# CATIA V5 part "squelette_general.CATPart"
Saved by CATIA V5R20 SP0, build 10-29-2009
Part number: squelette_general
Publications: "Plan_ref", "Point_A", "Point_B", "Point_C", "Point_D", "Point_E", "Point_F", "Point_debut_bati", "Projection_point_A_bati", "Projection_point_G_bati", "Projection_point_D_bati", "Point_fin_bati", "Point_fin_bascule_2", "Point_G"
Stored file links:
  C:\Users\J\IAO_2012_jgossard\squelette_general.CATPart
  C:\Users\J\IAO_2012_jgossard\squelette_mecanisme_presse.CATProduct

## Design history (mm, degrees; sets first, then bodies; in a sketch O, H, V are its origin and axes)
External parameters (linked from other documents)
  External.Longueur_AB = 5 mm
  External.Longueur_BC = 25 mm
  External.Longueur_CD = 60 mm
  External.Longueur_DE = 15 mm
  External.Longueur_EF = 15 mm
  External.Longueur_FG = 30 mm
Body1 (main body)
  Plane1 "Plan_ref": type Offset, RefPlane yz-plane, Offset 0
  Point1 "Point_A": type OnPlane, Support Plane1, H 10, V 15, Direction (0, 1, 0)
  Point2 "Point_B": type OnPlane, Support Plane1, RefPoint Point1, H 0, V 5 {= External.Longueur_AB}, Direction (0, 1, 0)
  Point3 "Point_C": type OnPlane, Support Plane1, RefPoint Point2, H 0, V 25 {= External.Longueur_BC}, Direction (0, 1, 0)
  Point4 "Point_D": type OnPlane, Support Plane1, RefPoint Point3, H 60 {= External.Longueur_CD}, V 7.5 {= External.Longueur_DE /2}, Direction (0, 1, 0)
  Point5 "Point_E": type OnPlane, Support Plane1, RefPoint Point4, H 0, V -15 {= -External.Longueur_DE}, Direction (0, 1, 0)
  Point6 "Point_F": type OnPlane, Support Plane1, RefPoint Point5, H 0, V -15 {= -External.Longueur_EF}, Direction (0, 1, 0)
  Point7 "Point_G": type OnPlane, Support Plane1, RefPoint Point1, H 30, V 0, Direction (0, 1, 0)
  Point8 "Point_debut_bati": type OnPlane, Support Plane1, H 0, V 0, Direction (0, 1, 0)
  Point9 "Projection_point_A_bati": type OnPlane, Support Plane1, H 10, V 0, Direction (0, 1, 0)
  Point10 "Projection_point_G_bati": type OnPlane, Support Plane1, H 40, V 0, Direction (0, 1, 0)
  Point11 "Projection_point_D_bati": type OnPlane, Support Plane1, H 70, V 0, Direction (0, 1, 0)
  Point12 "Point_fin_bati": type OnPlane, Support Plane1, H 80, V 0, Direction (0, 1, 0)
  Point13 "Point_fin_bascule_2": type OnPlane, Support Plane1, RefPoint Point7, H 30, V 5, Direction (0, 1, 0)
